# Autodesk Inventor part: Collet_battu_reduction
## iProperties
Shininess: 64.0
Length Units: 11269
Angle Units: 11279
Time Units: 11290
Mass Units: 11283
Length Display Precision: 3
Angle Display Precision: 2
Compacted: True
Part Number: Collet_battu_reduction
Document SubType Name: Modeling
Created: 2008-02
Material: Acier inoxydable, austénitique
Designer: Pascal
Density: 0.0
Volumn: 0.0
Area: 0.0
PropertySet Name: Model Information
Control State: 0
Master: False
Checked Out: False
DESIGNATION: Collet battu réduction
Author: Pascal
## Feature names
1. Révolution1 [Revolution]
